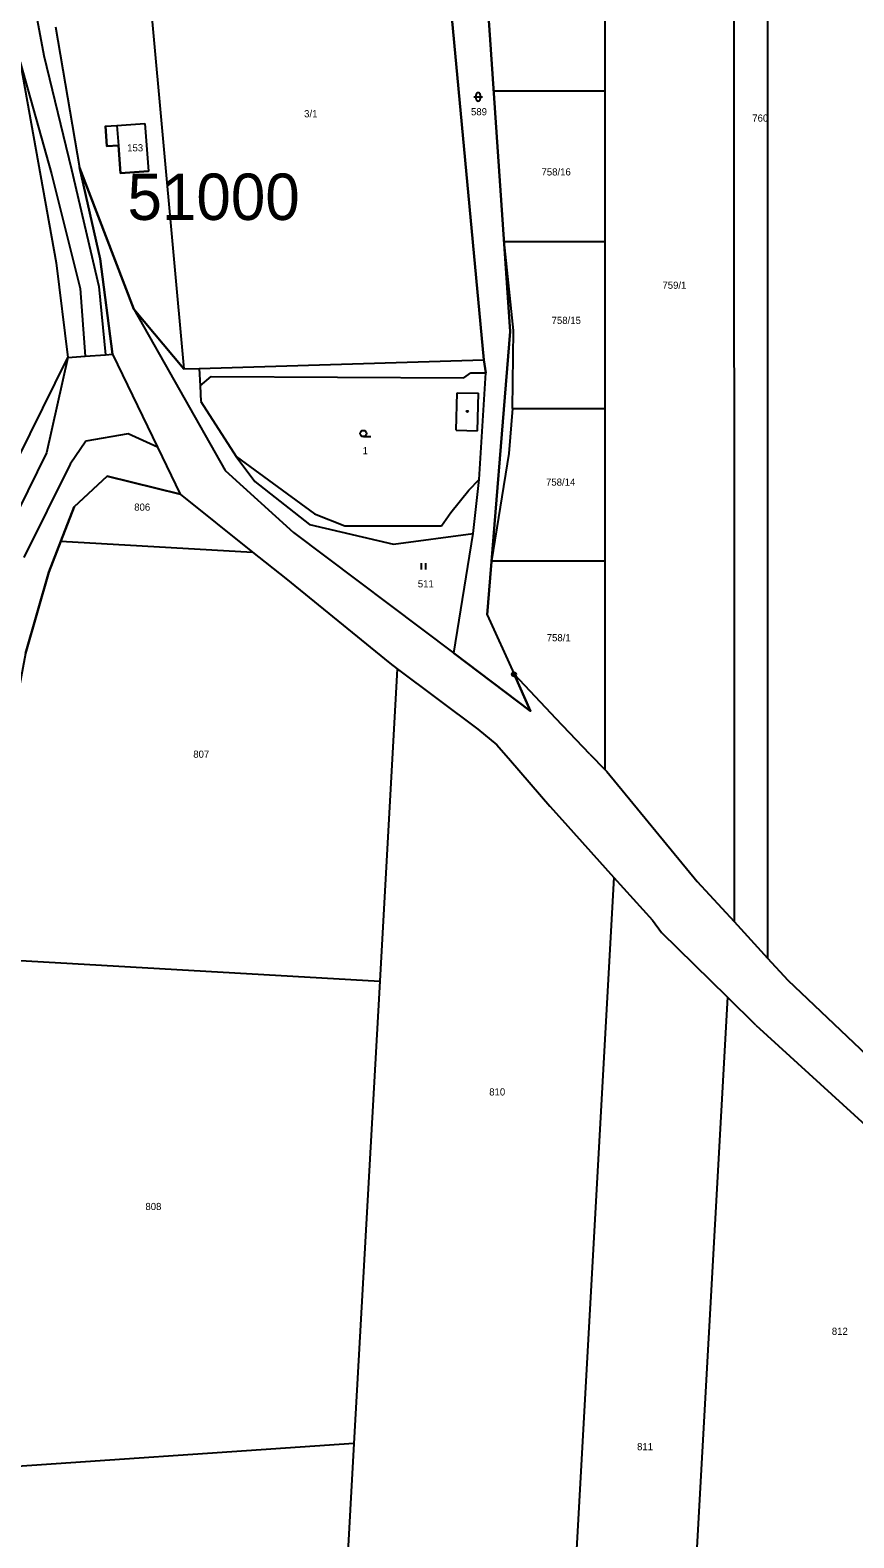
# Model space of a CAD drawing. Extents: x -725765 to -723182, y -1052705 to -1049154.
# Drawn here: x -724688.1 to -724492.6, y -1051438.8 to -1051081 of the extents above; entities that cross this region are included whole.
import ezdxf

# ---------------------------------------------------------------- set-up
doc = ezdxf.new("R2010")
doc.units = 0
for name, color, linetype in [('Vrstva 1', 7, 'Continuous'), ('Vrstva 18', 7, 'Continuous'), ('Vrstva 19', 7, 'Continuous'), ('Vrstva 25', 7, 'Continuous'), ('Vrstva 4', 7, 'Continuous'), ('Vrstva 52', 7, 'Continuous'), ('Vrstva 53', 7, 'Continuous')]:
    doc.layers.add(name, color=color, linetype=linetype)

msp = doc.modelspace()

# ---------------------------------------------------------------- linework, layer by layer
at = {"layer": 'Vrstva 1'}
for p, q in [((-724578.07, -1051095.44), (-724551.6, -1051095.4)), ((-724575.6, -1051131.18), (-724551.6, -1051131.14)), ((-724573.58, -1051170.82), (-724551.6, -1051170.82)), ((-724578.59, -1051206.92), (-724551.59, -1051206.96))]:
    msp.add_line(p, q, dxfattribs=at)
for points in [[(-724521.01, -1051029.6), (-724520.99, -1051292.58)], [(-724513.05, -1051031.07), (-724513.03, -1051301.26)], [(-724551.59, -1051256.55), (-724551.61, -1051033.11)], [(-724590.83, -1051047.49), (-724580.43, -1051159.22)], [(-724661.75, -1051050.29), (-724651.62, -1051161.43)], [(-724574.13, -1051152.55), (-724579.46, -1051075.24)], [(-724682.1, -1051080.22), (-724676.38, -1051113.58)], [(-724690.5, -1051088.58), (-724681.95, -1051136.24)], [(-724670.24, -1051103.8), (-724667.56, -1051103.63)], [(-724670.24, -1051103.8), (-724669.93, -1051108.58)], [(-724667.56, -1051103.63), (-724660.87, -1051103.19)], [(-724660.87, -1051103.19), (-724660.01, -1051114.45)], [(-724669.93, -1051108.58), (-724667.17, -1051108.39)], [(-724667.17, -1051108.39), (-724666.63, -1051115)], [(-724676.38, -1051113.58), (-724663.49, -1051147.21)], [(-724671.46, -1051135.3), (-724676.38, -1051113.58)], [(-724666.63, -1051115), (-724660.01, -1051114.45)], [(-724573.58, -1051170.82), (-724573.35, -1051152.32), (-724575.6, -1051131.18)], [(-724681.95, -1051136.24), (-724679.15, -1051158.68)], [(-724668.53, -1051157.94), (-724671.46, -1051135.3)], [(-724663.49, -1051147.21), (-724651.62, -1051161.43)], [(-724663.49, -1051147.21), (-724641.8, -1051185.53)], [(-724579.64, -1051219.74), (-724574.13, -1051152.55)], [(-724694.02, -1051188.82), (-724679.15, -1051158.68)], [(-724679.15, -1051158.68), (-724675.09, -1051158.4)], [(-724675.09, -1051158.4), (-724670.2, -1051158.06)], [(-724670.2, -1051158.06), (-724668.53, -1051157.94)], [(-724668.53, -1051157.94), (-724657.88, -1051179.95)], [(-724647.97, -1051161.32), (-724580.43, -1051159.22)], [(-724580.43, -1051159.22), (-724579.91, -1051162.36)], [(-724651.62, -1051161.43), (-724647.97, -1051161.32)], [(-724647.97, -1051161.32), (-724647.76, -1051165.4)], [(-724581.49, -1051187.62), (-724579.91, -1051162.36)], [(-724647.76, -1051165.4), (-724647.57, -1051169.16)], [(-724647.57, -1051169.16), (-724639.24, -1051182.23)], [(-724573.58, -1051170.82), (-724574.49, -1051181.47), (-724578.59, -1051206.92)], [(-724657.88, -1051179.95), (-724652.47, -1051191.12)], [(-724639.24, -1051182.23), (-724634.78, -1051188.14)], [(-724677.68, -1051194.15), (-724669.81, -1051186.83)], [(-724669.81, -1051186.83), (-724652.47, -1051191.12)], [(-724641.8, -1051185.53), (-724625.6, -1051200.25)], [(-724634.78, -1051188.14), (-724621.82, -1051198.3)], [(-724582.94, -1051200.49), (-724581.49, -1051187.62)], [(-724652.47, -1051191.12), (-724635.33, -1051204.87)], [(-724680.8, -1051202.26), (-724677.68, -1051194.15)], [(-724621.82, -1051198.3), (-724601.86, -1051203.03)], [(-724683.66, -1051209.67), (-724680.8, -1051202.26)], [(-724680.8, -1051202.26), (-724635.33, -1051204.87)], [(-724625.6, -1051200.25), (-724587.53, -1051228.89)], [(-724601.86, -1051203.03), (-724582.94, -1051200.49)], [(-724587.53, -1051228.89), (-724582.94, -1051200.49)], [(-724635.33, -1051204.87), (-724627.45, -1051211.19)], [(-724689.19, -1051228.95), (-724683.66, -1051209.67)], [(-724627.45, -1051211.19), (-724602.75, -1051231.25)], [(-724579.64, -1051219.74), (-724573.24, -1051233.89)], [(-724602.75, -1051231.25), (-724600.95, -1051232.6)], [(-724587.53, -1051228.89), (-724569.3, -1051242.6)], [(-724600.95, -1051232.6), (-724605.09, -1051306.69)], [(-724600.95, -1051232.6), (-724581.83, -1051246.94)], [(-724569.3, -1051242.6), (-724573.24, -1051233.89)], [(-724573.24, -1051233.89), (-724563.3, -1051244.36)], [(-724555.21, -1051252.82), (-724563.3, -1051244.36)], [(-724581.83, -1051246.94), (-724577.31, -1051250.66)], [(-724577.31, -1051250.66), (-724574.09, -1051254.32)], [(-724555.21, -1051252.82), (-724551.59, -1051256.55)], [(-724574.09, -1051254.32), (-724564.75, -1051265.18)], [(-724551.59, -1051256.55), (-724551.21, -1051256.95)], [(-724551.21, -1051256.95), (-724529.76, -1051283.02)], [(-724564.75, -1051265.18), (-724562.52, -1051267.62)], [(-724562.52, -1051267.62), (-724549.5, -1051282.1)], [(-724549.5, -1051282.1), (-724560.25, -1051474.27)], [(-724549.5, -1051282.1), (-724540.36, -1051292.26)], [(-724529.76, -1051283.02), (-724520.99, -1051292.58)], [(-724540.36, -1051292.26), (-724538.22, -1051295.13)], [(-724520.99, -1051292.58), (-724513.03, -1051301.26)], [(-724522.55, -1051310.53), (-724538.22, -1051295.13)], [(-724705.66, -1051300.92), (-724605.09, -1051306.69)], [(-724513.03, -1051301.26), (-724508.21, -1051306.51)], [(-724605.09, -1051306.69), (-724611.23, -1051416.43)], [(-724508.21, -1051306.51), (-724472.31, -1051340.56)], [(-724522.55, -1051310.53), (-724531.6, -1051472.32)], [(-724515.8, -1051317.16), (-724522.55, -1051310.53)], [(-724515.8, -1051317.16), (-724479.88, -1051349.89)], [(-724611.23, -1051416.43), (-724703.99, -1051422.72)], [(-724611.23, -1051416.43), (-724614.68, -1051477.96)]]:
    msp.add_lwpolyline(points, dxfattribs=at)
at = {"layer": 'Vrstva 25'}
for points in [[(-724582.75, -1051096.86), (-724580.75, -1051096.86)], [(-724582.25, -1051097.36), (-724582.25, -1051096.36)], [(-724581.25, -1051096.36), (-724581.25, -1051097.36)], [(-724609.01, -1051177.49), (-724607.26, -1051177.49)], [(-724595.21, -1051209.04), (-724595.21, -1051207.54)], [(-724594.17, -1051209.04), (-724594.17, -1051207.54)]]:
    msp.add_lwpolyline(points, dxfattribs=at)
for centre, radius in [((-724584.32, -1051171.5), 0.175), ((-724609.01, -1051176.74), 0.75), ((-724573.24, -1051233.89), 0.5), ((-724573.24, -1051233.89), 0.032)]:
    msp.add_circle(centre, radius, dxfattribs=at)
for centre, start, end in [((-724581.75, -1051096.36), 0.101, 180.0014), ((-724581.75, -1051097.36), 180.1024, 0.0029)]:
    msp.add_arc(centre, 0.5, start, end, dxfattribs=at)
at = {"layer": 'Vrstva 4'}
for points in [[(-724688.11, -1051069.6), (-724684.86, -1051087.02)], [(-724690.5, -1051088.58), (-724683.08, -1051115.08)], [(-724684.86, -1051087.02), (-724678.3, -1051114.08)], [(-724667.56, -1051103.63), (-724667.17, -1051108.39)], [(-724683.08, -1051115.08), (-724676.26, -1051142.37)], [(-724678.3, -1051114.08), (-724671.79, -1051141.84)], [(-724671.79, -1051141.84), (-724670.2, -1051158.06)], [(-724676.26, -1051142.37), (-724675.09, -1051158.4)], [(-724679.15, -1051158.68), (-724684.23, -1051181.31)], [(-724647.76, -1051165.4), (-724645.14, -1051163.2)], [(-724645.14, -1051163.2), (-724585.16, -1051163.54)], [(-724585.16, -1051163.54), (-724583.47, -1051162.33)], [(-724583.47, -1051162.33), (-724579.91, -1051162.36)], [(-724586.95, -1051175.97), (-724586.74, -1051167.08)], [(-724586.74, -1051167.08), (-724581.66, -1051167.2)], [(-724581.88, -1051176.13), (-724581.66, -1051167.2)], [(-724664.88, -1051176.81), (-724674.89, -1051178.57)], [(-724657.88, -1051179.95), (-724664.88, -1051176.81)], [(-724586.95, -1051175.97), (-724581.88, -1051176.13)], [(-724684.23, -1051181.31), (-724695.49, -1051204.01)], [(-724674.89, -1051178.57), (-724678.63, -1051184.02)], [(-724678.63, -1051184.02), (-724689.65, -1051206.15)], [(-724639.24, -1051182.23), (-724620.57, -1051195.82)], [(-724583.98, -1051190.22), (-724581.49, -1051187.62)], [(-724588.21, -1051195.45), (-724583.98, -1051190.22)], [(-724620.57, -1051195.82), (-724613.43, -1051198.66)], [(-724590.45, -1051198.63), (-724588.21, -1051195.45)], [(-724613.43, -1051198.66), (-724590.45, -1051198.63)]]:
    msp.add_lwpolyline(points, dxfattribs=at)
at = {"layer": 'Vrstva 52'}
for points in [[(-724579.46, -1051075.24), (-724574.13, -1051152.55), (-724579.64, -1051219.74), (-724573.24, -1051233.89), (-724569.3, -1051242.6), (-724587.53, -1051228.89), (-724582.94, -1051200.49), (-724581.49, -1051187.62), (-724579.91, -1051162.36), (-724580.43, -1051159.22), (-724590.83, -1051047.49)], [(-724661.75, -1051050.29), (-724651.62, -1051161.43), (-724663.49, -1051147.21), (-724676.38, -1051113.58), (-724671.46, -1051135.3), (-724668.53, -1051157.94), (-724657.88, -1051179.95), (-724652.47, -1051191.12), (-724669.81, -1051186.83), (-724677.68, -1051194.15), (-724680.8, -1051202.26), (-724683.66, -1051209.67), (-724689.19, -1051228.95), (-724692.56, -1051246.84), (-724705.66, -1051300.92), (-724706.33, -1051303.7), (-724709.12, -1051325.51), (-724709.36, -1051330.78), (-724711.42, -1051347.65), (-724710.86, -1051374.28), (-724707, -1051403.67), (-724703.99, -1051422.72), (-724702.54, -1051431.88), (-724694, -1051475.83)], [(-724660.87, -1051103.19), (-724660.01, -1051114.45), (-724666.63, -1051115), (-724667.17, -1051108.39), (-724669.93, -1051108.58), (-724670.24, -1051103.8), (-724667.56, -1051103.63), (-724660.87, -1051103.19)]]:
    msp.add_lwpolyline(points, dxfattribs=at)

# ---------------------------------------------------------------- texts
at = {"layer": 'Vrstva 18'}
for s, p in [('3/1', (-724623.07, -1051101.71)), ('589', (-724583.45, -1051101.23)), ('760', (-724516.67, -1051102.73)), ('758/16', (-724566.71, -1051115.51)), ('759/1', (-724538, -1051142.4)), ('758/15', (-724564.31, -1051150.75)), ('1', (-724609.19, -1051181.67)), ('758/14', (-724565.64, -1051189.13)), ('806', (-724663.41, -1051195.06)), ('511', (-724596.08, -1051213.26)), ('758/1', (-724565.47, -1051226.05)), ('807', (-724649.39, -1051253.69)), ('810', (-724579.12, -1051333.84)), ('808', (-724660.75, -1051361.03)), ('812', (-724497.78, -1051390.64)), ('811', (-724544.02, -1051418.03))]:
    msp.add_text(s, height=1.7, dxfattribs=at).set_placement(p)
at = {"layer": 'Vrstva 19'}
msp.add_text('153', height=1.7, dxfattribs=at).set_placement((-724665.08, -1051109.79))
at = {"layer": 'Vrstva 53'}
msp.add_text('51000', height=11, dxfattribs=at).set_placement((-724665.01, -1051126.06))

doc.saveas('drawing.dxf')
